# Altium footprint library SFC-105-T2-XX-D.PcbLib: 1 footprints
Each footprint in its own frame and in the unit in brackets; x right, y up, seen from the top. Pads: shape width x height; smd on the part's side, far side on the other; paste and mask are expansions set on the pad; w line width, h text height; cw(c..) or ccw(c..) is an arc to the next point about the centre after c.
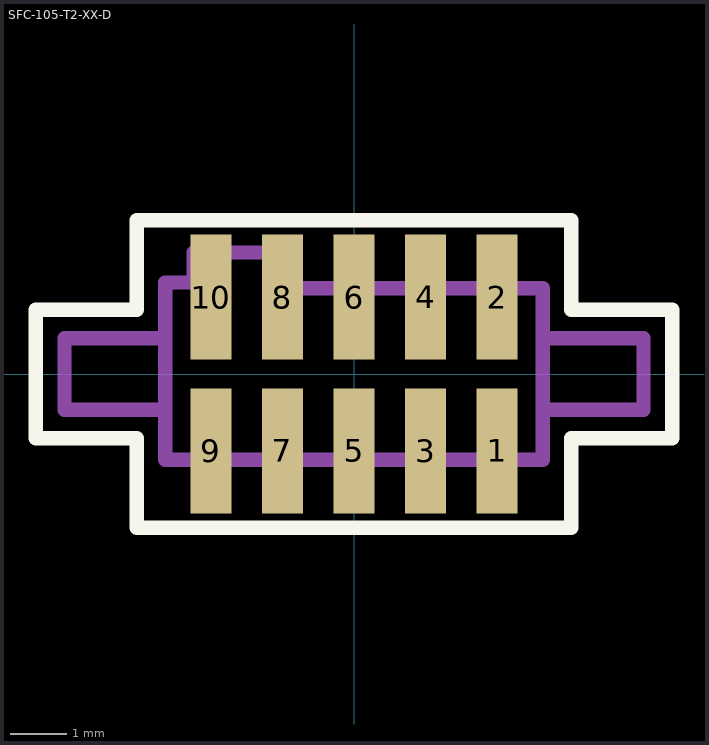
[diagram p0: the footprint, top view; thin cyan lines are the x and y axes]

## SFC-105-T2-XX-D [mil]
pads (10):
  rect 29x87.5 smd mask+2: 1(100,-53.75) 2(100,53.75) 3(50,-53.75) 4(50,53.75) 5(0,-53.75) 6(0,53.75) 7(-50,-53.75) 8(-50,53.75) 9(-100,-53.75) 10(-100,53.75)
Top Overlay:
  lines w10: -222.5,-45 -222.5,45 -152,45 -152,107.5 152,107.5 152,45 222.5,45 222.5,-45 152,-45 152,-107.5 -152,-107.5 -152,-45 -222.5,-45
Mechanical 1:
  lines w10: -132,-25 -202.5,-25 -202.5,25 -132,25 ; 132,-25 202.5,-25 202.5,25 132,25 ; -132,-60 -132,64.04 -112,64.04 -112,85 -52,85 -52,60 132,60 132,-60 -132,-60
  text "J1" at -17.57,-18 h30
